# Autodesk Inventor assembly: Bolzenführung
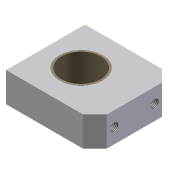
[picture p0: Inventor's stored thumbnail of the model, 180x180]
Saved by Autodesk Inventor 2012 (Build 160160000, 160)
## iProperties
Company: CAD-Verlag
Created: 2004-09
Part Number: Bolzenführung
Document SubType Name: Assembly
Designer: Greiling
Manufacturer: Standard
Standards Organization: Custom
Checked By: Jürgen Kronas
Stock Number: 10-10016
Author: Juergen Kronas
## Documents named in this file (3)
- C:\Daten Vault 2012 Inventor\Kapitel 6\6.2\Anschlag\Bolzenführung.iam
- C:\Daten Vault 2012 Inventor\Kapitel 6\6.2\Anschlag\Bolzenführung_einzel.ipt
- C:\Daten Vault 2012 Inventor\Kapitel 6\6.2\Anschlag\DU-Buchse.ipt
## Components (2 placed, 2 different names)
1. Bolzenführung_einzel:1 — Fluchtend:1
2. DU-Buchse:1 — Fluchtend:1
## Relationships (1: Flush 1)
- Fluchtend:1 [Flush]: Bolzenführung_einzel:1 ↔ DU-Buchse:1
